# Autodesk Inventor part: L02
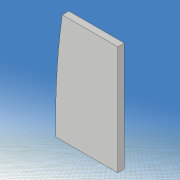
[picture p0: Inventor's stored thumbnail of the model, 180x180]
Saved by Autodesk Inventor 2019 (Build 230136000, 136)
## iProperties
Created: 2021-05
Part Number: L02
Material: 一般
Document SubType Name: Modeling
Designer: kikut
Density: 1 g/cm^3
Appearance: 既定
Mass: 0.00934248 g
Surface Area: 0.426451 cm^2
Volume: 0.00934248 cm^3
Author: kikut
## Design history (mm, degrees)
sketch "スケッチ1"
  geometry: L1 (80, 60)-(-80, 60); L2 (-80, 60)-(-80, -60); L3 (-80, -60)-(80, -60); L4 (80, -60)-(80, 60); L5 (80, 60)-(-80, -60); L6 (-80, 60)-(80, -60); 1 further point
  constraints: 12 end point, 2 midpoint, 2 parallel, 1 horizontal, 1 perpendicular
  dimensions: "d0" = 160 distance of L2.end L3.end; "d1" = 120 distance of L1.end L2.end
extrude "押し出し1" new body sketch "スケッチ1" stored distance "d2" = 0.6; taper "d3" = 0 deg
sketch "スケッチ2"
  geometry: L1 (-140, 0)-(140, 0) reference; L2 (0, -54)-(20, -30); L3 (0, 54)-(20, 30); L4 (0, -3)-(6.514, -3); L5 (6.514, -3)-(16, -6); L6 (16, -6)-(24, -3); L7 (24, -3)-(33.716, -3); L8 (0, 3)-(6.514, 3); L9 (6.514, 3)-(16, 6); L10 (16, 6)-(24, 3); L11 (24, 3)-(33.716, 3); L12 (0, -98)-(0, 98) reference; L13 (-100, -70)-(100, -70); L14 (100, -70)-(100, 70); L15 (100, 70)-(-100, 70); L16 (-100, 70)-(-100, -70); L17 (-100, -70)-(100, 70); L18 (100, -70)-(-100, 70); A1 r 60 centre (54.312, 28.5) between (0, 54) and (0, 3); A2 r 60 centre (54.312, -28.5) between (0, -3) and (0, -54); A3 r 18.111 centre (18, -12) between (20, -30) and (33.716, -3); A4 r 18.111 centre (18, 12) between (33.716, 3) and (20, 30); 1 further point
  constraints: 32 end point, 8 point on circle, 8 symmetric about line, 4 centre point, 3 horizontal, 2 collinear, 2 midpoint, 2 parallel, 1 perpendicular
  dimensions: "d5" = 60 radius of A1; "d6" = 6 distance of L8.start L4.start; "d7" = 108 distance of L3.start L2.start; "d8" = 0 horizontal distance of L3.start L8.start; "d9" = 60 distance of L3.end L2.end; "d10" = 0 horizontal distance of point (0, 0) L3.start; "d11" = 20 horizontal distance of L3.start L3.end; "d12" = 24 distance of A4.centre A3.centre; "d13" = 6 distance of L11.end L7.end; "d14" = 12 distance of L9.end L5.end; "d15" = 16 distance from line of L12 L5.end; "d16" = 24 distance from line of L6.end L12; "d17" = 200 distance of L14.end L15.end; "d18" = 140 distance of L15.end L13.start; "d30" = 18 distance from line of L12 A4.centre
extrude "押し出し2" cut sketch "スケッチ2" stored distance "d19" = 10; taper "d20" = 0 deg
sketch "スケッチ3"
  geometry: L1 (49.705, -17.97)-(33.948, -15.191); L2 (33.948, -15.191)-(34.295, -13.222); L3 (34.295, -13.222)-(50.052, -16); L4 (50.052, -16)-(49.705, -17.97); L5 (49.705, -17.97)-(34.295, -13.222); L6 (33.948, -15.191)-(50.052, -16); L7 (50.052, 16)-(34.295, 13.222); L8 (34.295, 13.222)-(33.948, 15.191); L9 (33.948, 15.191)-(49.705, 17.97); L10 (49.705, 17.97)-(50.052, 16); L11 (50.052, 16)-(33.948, 15.191); L12 (34.295, 13.222)-(49.705, 17.97); L13 (-112, 0)-(112, 0) reference; L14 (0, -84)-(0, 84) reference; 3 further points
  constraints: 24 end point, 4 midpoint, 4 parallel, 2 perpendicular, 2 symmetric about line
  dimensions: "d21" = 2 distance of L3.end L1.start; "d22" = 2 distance of L9.end L7.start; "d23" = 16 distance of L8.end L9.end; "d24" = 42 distance from line of L14 point (42, 15.596); "d26" = 10 deg angle of L7 L13; "d62" = 16 distance from line of L3.end L13
extrude "押し出し3" join sketch "スケッチ3" distance "d27" = 0.6; taper "d28" = 0 deg
fillet "フィレット1" dims "d31" = 2
fillet "フィレット2" dims "d32" = 1
sketch "スケッチ7"
  geometry: L1 (-20, 60)-(80, 60); L2 (80, 60)-(80, -60); L3 (80, -60)-(-20, -60); L4 (-20, -60)-(-20, 60); L5 (0, -82.207)-(0, 85.793) reference; L6 (-40, 0)-(100, 0) reference; L7 (-10, -20)-(0, -20); L8 (0, -20)-(0, -30); L9 (0, -30)-(-10, -30); L10 (-10, -30)-(-10, -20); 1 further point
  constraints: 16 end point, 4 parallel, 2 horizontal, 2 perpendicular, 1 other
  dimensions: "d80" = 120 distance of L3.end L1.start; "d81" = 20 distance between parallel lines of L5 L4; "d82" = 100 distance of L1.start L1.end; "d84" = 10 distance of L8.end L9.end; "d85" = 10 distance of L7.end L8.end; "d86" = 10 distance between parallel lines of L4 L10; "d89" = 30 distance between parallel lines of L3 L9
extrude "押し出し5" cut sketch "スケッチ7" stored distance "d87" = 10; taper "d88" = 0 deg
node "ソリッド1"
